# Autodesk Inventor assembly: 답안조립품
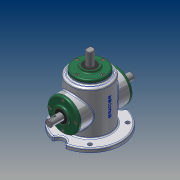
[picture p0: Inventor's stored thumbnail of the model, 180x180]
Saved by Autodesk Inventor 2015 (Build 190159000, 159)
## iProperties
Created: 2018-04
Part Number: 답안조립품
Document SubType Name: Assembly
Designer: user
Author: user
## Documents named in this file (16)
- C:\Users\user\Desktop\480407V1031\답안조립품.iam
- C:\Users\user\Desktop\480407V1031\본체.ipt
- C:\Users\user\Desktop\480407V1031\메인 베벨기어.ipt
- C:\Users\user\Desktop\480407V1031\메인 축.ipt
- 메인 축.ipt
- C:\Users\user\Desktop\480407V1031\베어링 6203.ipt
- C:\Users\user\Desktop\480407V1031\볼트 M4.ipt
- 볼트 M4.ipt
- C:\Users\user\Desktop\480407V1031\서브 베벨기어.ipt
- C:\Users\user\Desktop\480407V1031\서브 축.ipt
- 서브 축.ipt
- C:\Users\user\Desktop\480407V1031\오일 실.ipt
- 오일 실.ipt
- C:\Users\user\Desktop\480407V1031\커버.ipt
- C:\Users\user\Desktop\480407V1031\키 4x4.ipt
- C:\Users\user\Desktop\480407V1031\키 5x5.ipt
## Named parameters: d6_d4 = 0, d7_d5 = 0, d13_d4 = 0, d14_d5 = 0, d15_d8 = 0, d16_d9 = 180 deg, d17_d10 = 0, d18_d11 = 0, d19_d12 = 0
